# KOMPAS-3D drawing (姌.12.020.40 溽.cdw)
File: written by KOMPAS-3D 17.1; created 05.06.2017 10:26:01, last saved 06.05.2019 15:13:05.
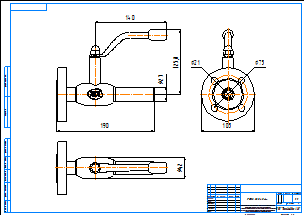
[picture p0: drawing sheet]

Sheet 1: A2, landscape

Title block, sheet 1: name: КШ.12.020.40 фс; material: Внимание! Данный продукт является объектом авторского права ООО «Торговый Дом АДЛ». / Запрещается изменение, копирование, распространение / (в том числе путем копирования на другие сайты и ресурсы в Интернете) / или любое иное использование информации и объектов без предварительного / согласия правообладателя (ООО «Торговый Дом АДЛ»).; sheets: 1; organisation: ООО "Торговый дом АДЛ"; sheet format: A2; stored path: C:\Users\kka\KOMPAS_Work\Модели кранов для исследований\Все краники\Редуцированный резьба-сварка ШК БИВАЛ\КШ.02.015.40 рс.cdw

Views: Вид 1, Проекционный вид 2, Проекционный вид 3
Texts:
  Klimkovich
  ADL
Dimensions and other numbers on the sheet: 140; 27; 125,8; 190; 105; 75; 21; 42; 1:1; 1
